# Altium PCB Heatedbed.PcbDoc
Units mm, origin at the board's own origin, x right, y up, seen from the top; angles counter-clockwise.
Board outline 257 x 229 mm, 2 copper layers (Top Layer, Bottom Layer); 12 components, 3 nets, 16 pads, 0 vias.
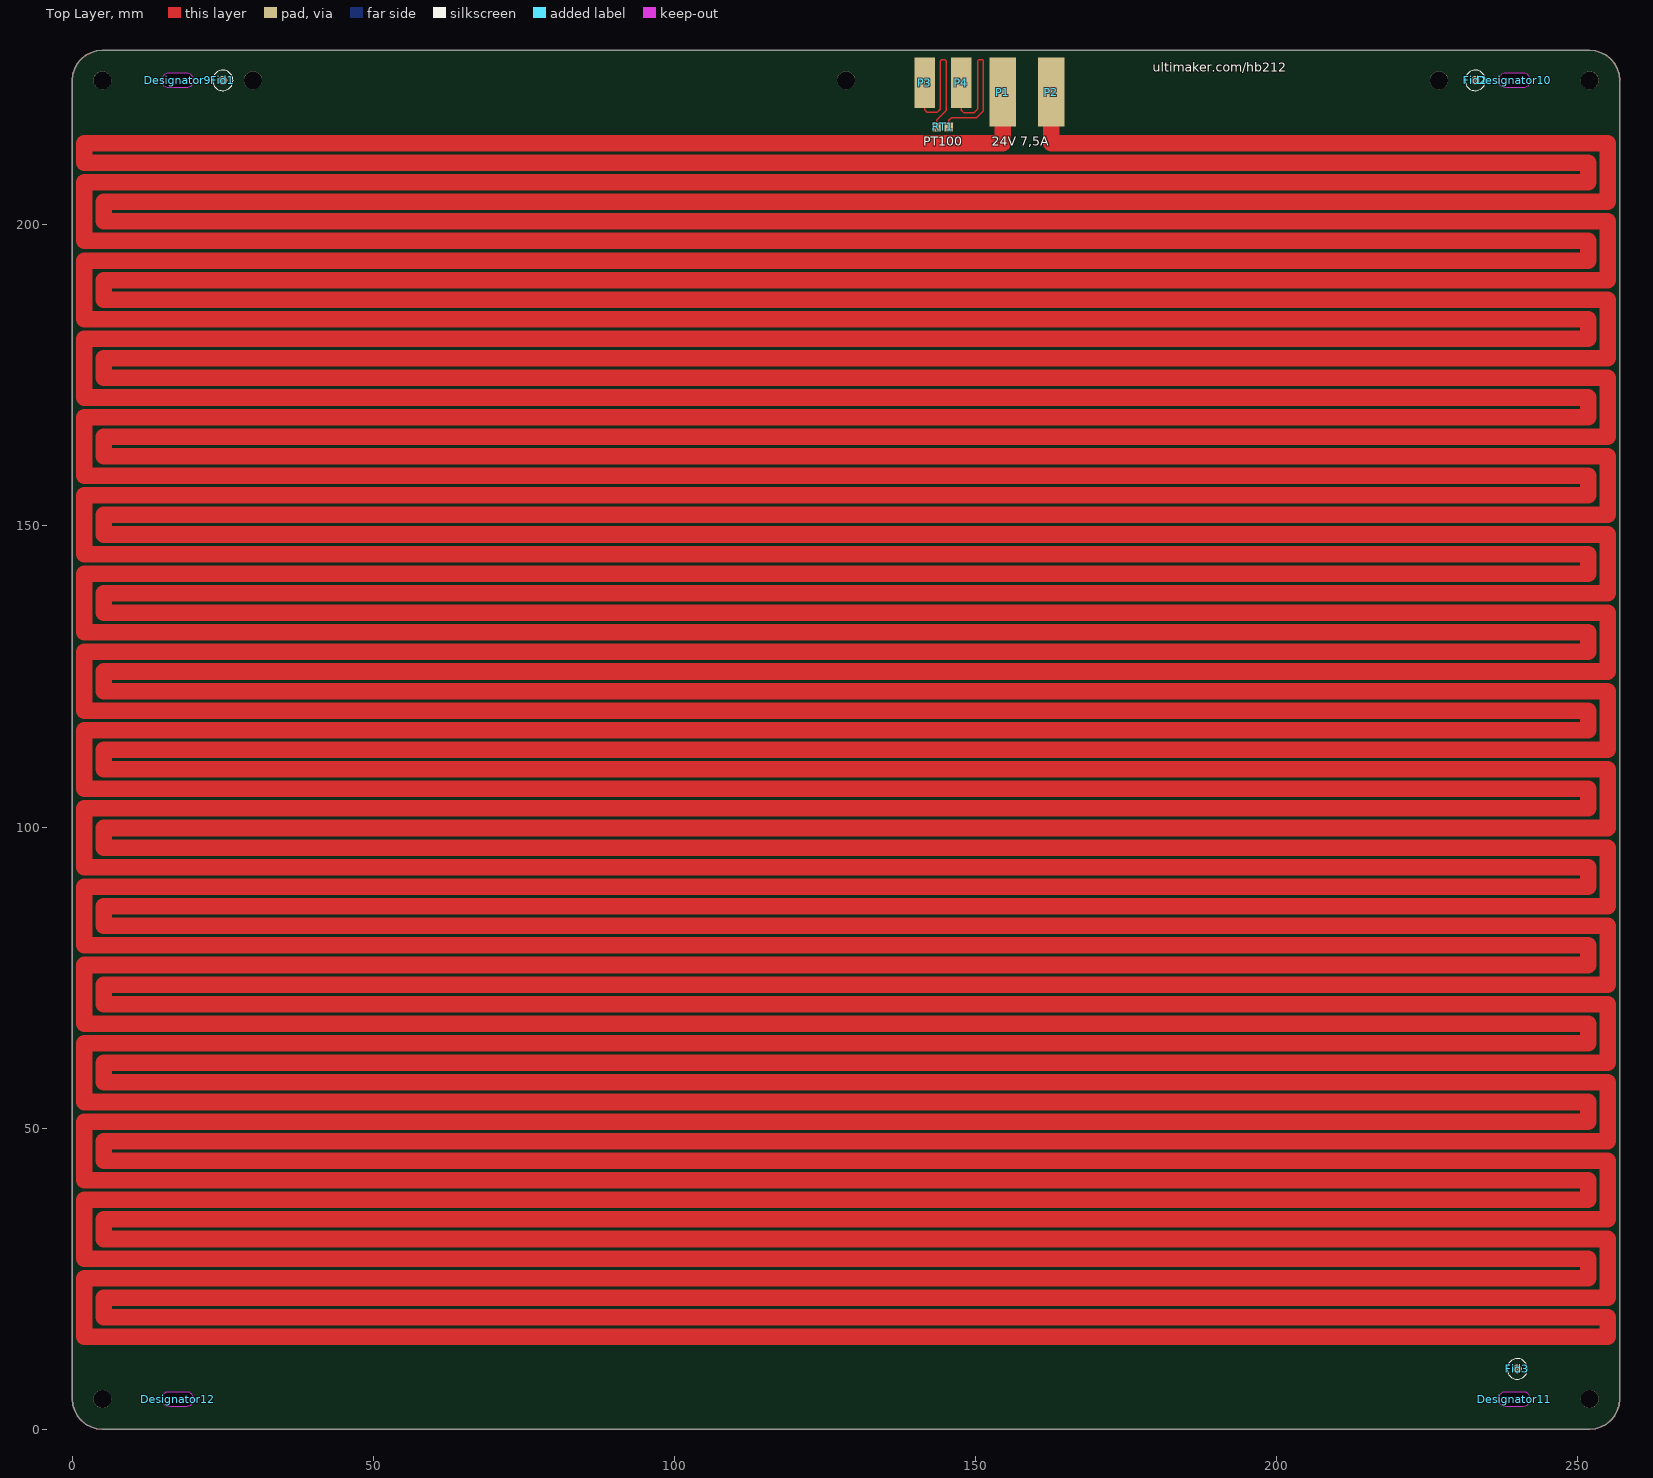
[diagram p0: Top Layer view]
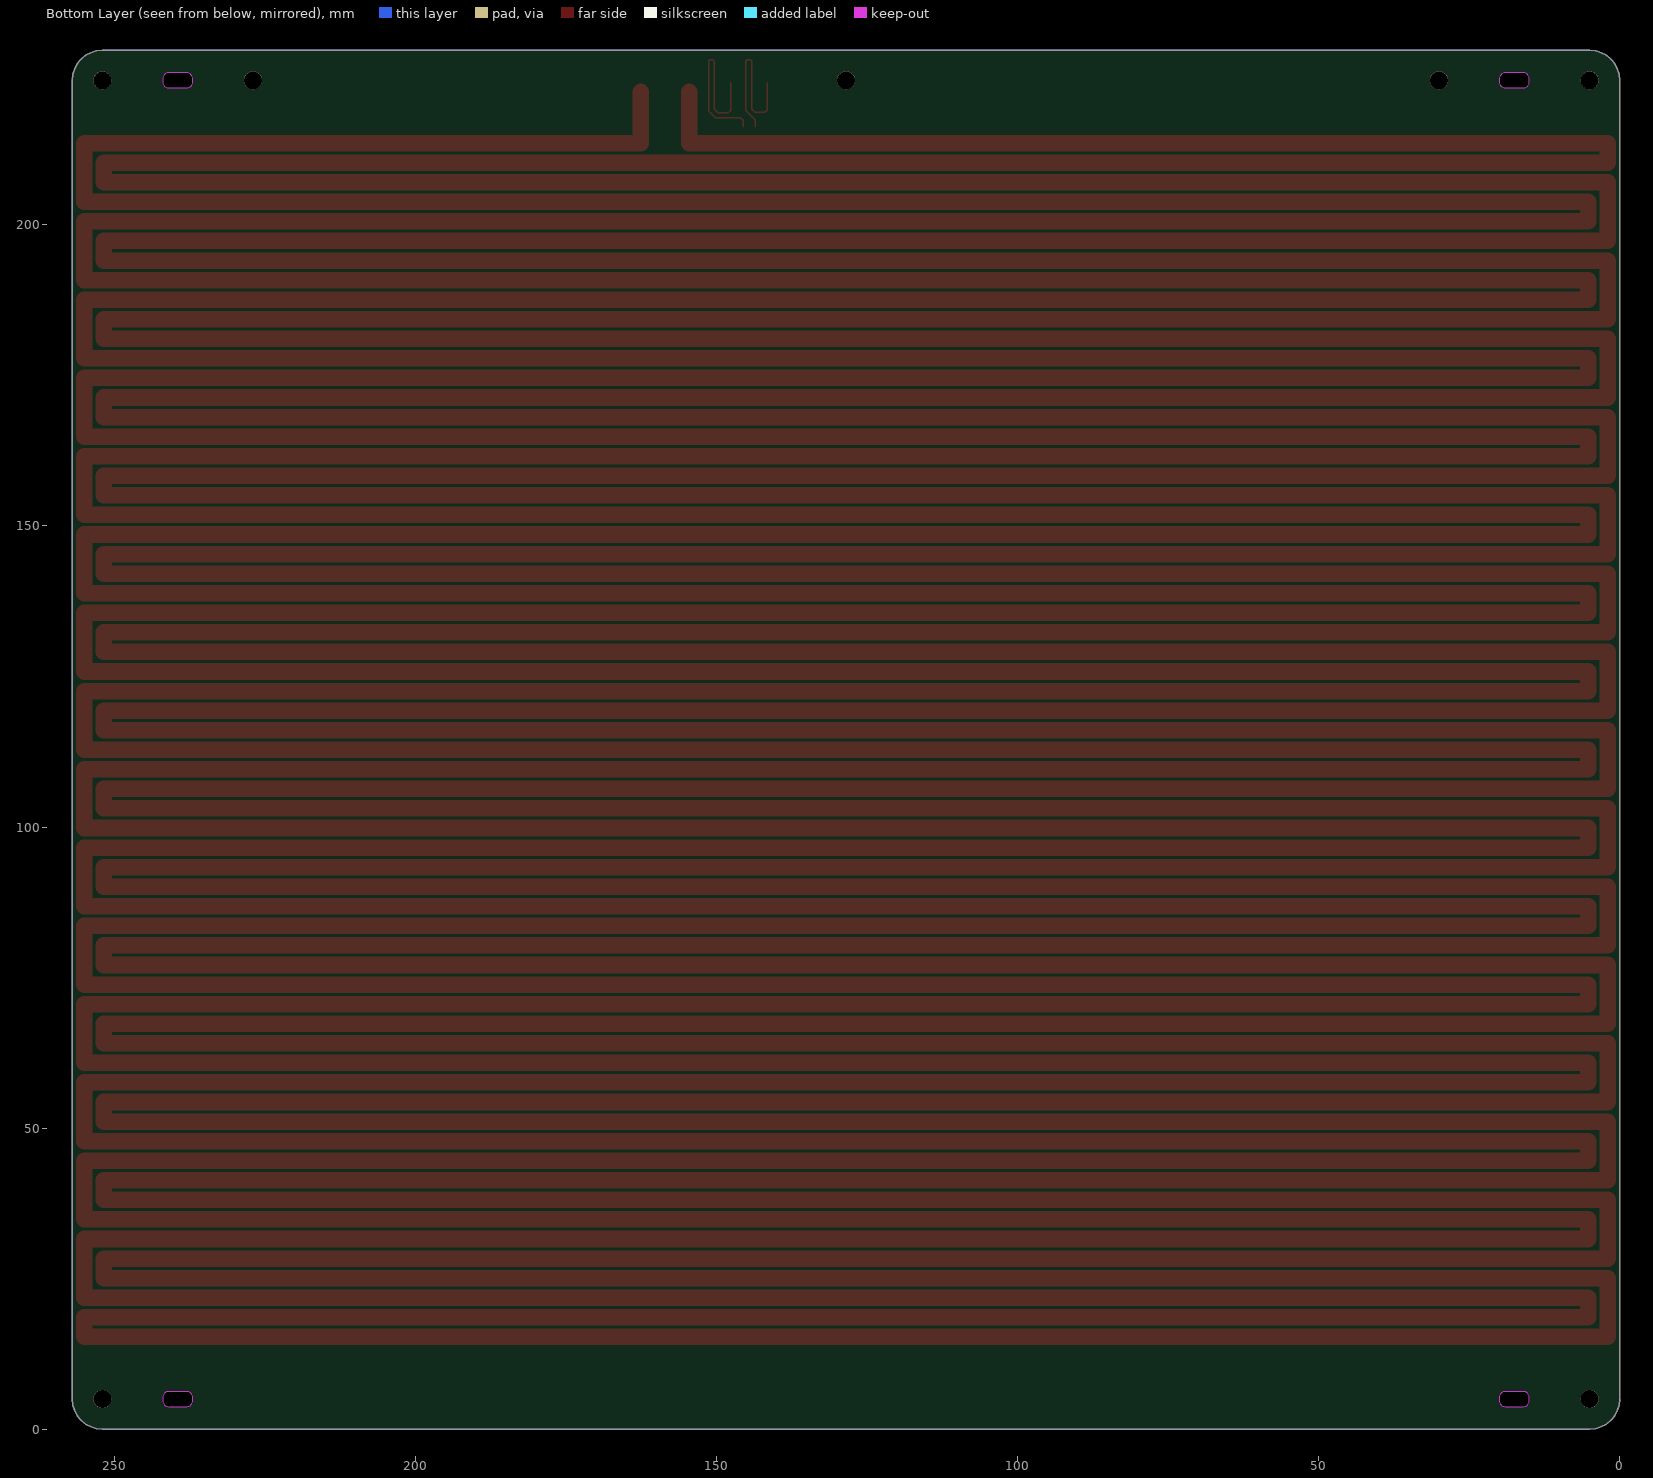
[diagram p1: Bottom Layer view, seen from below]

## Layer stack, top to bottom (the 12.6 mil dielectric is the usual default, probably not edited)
Top Solder: solder mask 0.0102, Solder Resist, Dk 3.5
Top Layer: signal copper 0.0356
Dielectric 1: dielectric 0.32, FR-4, Dk 4.8
Bottom Layer: signal copper 0.0356
Bottom Solder: solder mask 0.0102, Solder Resist, Dk 3.5

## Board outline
0.381,3.086 0.097,4.023 0,4.999 0,224.002 0.097,224.978 0.381,225.915 0.843,226.779 1.463,227.538 2.222,228.158 3.086,228.62 4.023,228.905 5.001,229.001 251.998,229.001 252.976,228.905 253.914,228.62 254.777,228.158 255.534,227.538 256.156,226.779 256.619,225.915 256.903,224.978 257,224.002 257,4.999 256.903,4.023 256.619,3.086 256.156,2.222 255.534,1.463 254.777,0.841 253.914,0.381 252.976,0.094 251.998,0 5.002,0 4.023,0.094 3.086,0.381 2.222,0.841 1.463,1.463 0.843,2.222

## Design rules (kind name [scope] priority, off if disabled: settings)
Clearance [All] p1: gap=0.203
HoleSize [All] p1: absolutevalues=TRUE maxlimit=4.3 minlimit=0.025 maxpercent=80.000 minpercent=20.000
MinimumSolderMaskSliver [All] p1 off: minsoldermaskwidth=0.051
PlaneClearance [All] p1: clearance=0.203
PlaneConnect [All] p1: planeconnectstyle=Relief reliefexpansion=0.203 reliefentries=4 reliefconductorwidth=0.203 reliefairgap=0.203
PolygonConnect [All] p1: connectstyle=Relief reliefconductorwidth=0.254 reliefentries=4 polygonreliefangle="90 Angle" airgapwidth=0.254
RoomDefinition Heatedbed [InComponentClass('Heatedbed')] p1 off: confinementstyle=ConfineIn formatcopy=TRUE lockcomponents=FALSE outline 301.042,-142.701 318.392,-142.701 318.392,-138.126 301.042,-138.126
RoutingVias [All] p1: holewidth=0.3 width=0.6 viastyle="Through Hole" minholewidth=0.3 minwidth=0.6 maxholewidth=1 maxwidth=3
SilkToSilkClearance [All] p1: silktosilkclearance=0
SilkToSolderMaskClearance SilkscreenOverComponentPads [IsPad] p1: minsilkscreentomaskgap=0.127 clearancetoexposedcopper=TRUE
SolderMaskExpansion [All] p1: expansion=0.102
Width [All] p1: maxlimit=10 minlimit=0.203 preferedwidth=0.203
24 further rules are at their usual default settings.

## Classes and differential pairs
component class Heatedbed: Fid1 Fid2 Fid3 P1 P2 P3 P4 RT1

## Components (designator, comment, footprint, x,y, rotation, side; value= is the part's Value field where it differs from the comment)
Designator9 "Comment" Hole 17.5,224 r0 top locked
Designator10 "Comment" Hole 239.5,224 r0 top locked
Designator11 "Comment" Hole 239.5,5 r0 top locked
Designator12 "Comment" Hole 17.5,5 r0 top locked
Fid1 "Fiducial" FIDUCIAL 25,224 r0 top locked
Fid2 "Fiducial" FIDUCIAL 233,224 r0 top locked
Fid3 "Fiducial" FIDUCIAL 240,10 r0 top locked
P1 "Power 1" "AVX POKE HOME CONTACT" 154.56,222.069 r90 top locked
P2 "Power 2" "AVX POKE HOME CONTACT" 162.56,222.069 r90 top locked
P3 "PT100 1" "AVX POKE HOME CONTACT 3MM" 141.6,223.575 r90 top
P4 "PT100 2" "AVX POKE HOME CONTACT 3MM" 147.65,223.575 r90 top
RT1 "PT100 0805" 6-0805_M 144.575,216.275 r0 top locked

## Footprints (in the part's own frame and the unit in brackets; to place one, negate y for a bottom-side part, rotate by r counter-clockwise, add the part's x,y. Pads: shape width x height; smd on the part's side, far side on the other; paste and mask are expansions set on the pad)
6-0805_M [mm] "Chip Resistor, Body 2.0x1.2mm, IPC Low Density"
  rect 1.4x1.5 smd: 1(-1,0) 2(1,0)
  silkscreen extent 0,-0.65 0,0.65, body extent -1.07,-0.7 1.07,0.7, height 0.7
"AVX POKE HOME CONTACT" [mm] "AVX 70-9296-001-004-006"
  rect 11.4x4.4 smd: 1(0,0)
  body extent -5.5,-2 5.5,2, height 4
"AVX POKE HOME CONTACT 3MM" [mm] "AVX 70-9296-001-003-006"
  rect 8.4x3.4 smd: 1(0,0)
  body extent -4,-1.5 4,1.5, height 3
FIDUCIAL [mm] "Fiducial"
  round 1.5 smd paste-20 mask+0.9: ""(0,0)
  silkscreen extent -1.7,-1.7 1.7,1.7
Hole [mm]
  Keep-Out Layer board cut-out: -2.331,-0.805 -2.424,-0.633 -2.481,-0.445 -2.499,-0.25 -2.499,0.25 -2.481,0.445 -2.424,0.633 -2.331,0.806 -2.207,0.957 -2.055,1.081 -1.882,1.174 -1.695,1.23 -1.5,1.25 1.5,1.25 1.696,1.23 1.883,1.174 2.057,1.081 2.207,0.957 2.333,0.806 2.425,0.633 2.481,0.445 2.501,0.25 2.501,-0.25 2.481,-0.445 2.425,-0.633 2.333,-0.805 2.207,-0.956 2.057,-1.082 1.883,-1.174 1.696,-1.231 1.5,-1.25 -1.5,-1.25 -1.695,-1.231 -1.882,-1.174 -2.055,-1.082 -2.207,-0.956

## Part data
Fid1 Fid2 Fid3: library part Library_MISC-0003
P1 P2 P3 P4: library part Plug, "Plug"
RT1: library part "Res Thermal", "Thermistor"

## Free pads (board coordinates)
  round 3 hole 3 unplated: 0(5,5) 0(5,224) 0(30,224) 0(128.5,224) 0(227,224) 0(252,5) 0(252,224)

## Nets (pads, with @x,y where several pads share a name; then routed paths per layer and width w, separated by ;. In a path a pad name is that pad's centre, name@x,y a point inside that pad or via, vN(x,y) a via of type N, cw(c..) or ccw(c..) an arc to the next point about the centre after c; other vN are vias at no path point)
$Net2: P1.1 P2.1 | length 15896.4
  Top Layer w2.751: 1.994,213.589 1.994,210.332 251.744,210.332 251.744,207.081 1.994,207.081 1.994,197.333 251.744,197.333 251.744,194.081 1.994,194.081 1.994,184.333 251.744,184.333 251.744,181.082 1.994,181.082 1.994,171.333 251.744,171.333 251.744,168.082 1.994,168.082 1.994,158.333 251.744,158.333 251.744,155.082 1.994,155.082 1.994,145.331 251.744,145.331 251.744,142.083 1.994,142.083 1.994,132.331 251.744,132.331 251.744,129.083 1.994,129.083 1.994,119.332 251.744,119.332 251.744,116.083 1.994,116.083 1.994,106.332 251.744,106.332 251.744,103.083 1.994,103.083 1.994,93.332 251.744,93.332 251.744,90.081 1.994,90.081 1.994,80.333 251.744,80.333 251.744,77.081 1.994,77.081 1.994,67.333 251.744,67.333 251.744,64.082 1.994,64.082 1.994,54.333 251.744,54.333 251.744,51.082 1.994,51.082 1.994,41.333 251.744,41.333 251.744,38.082 1.994,38.082 1.994,28.331 251.744,28.331 251.744,25.082 1.994,25.082 1.994,15.331 254.993,15.331 254.993,18.583 5.245,18.583 5.245,21.831 254.993,21.831 254.993,31.582 5.245,31.582 5.245,34.831 254.993,34.831 254.993,44.582 5.245,44.582 5.245,47.833 254.993,47.833 254.993,57.582 5.245,57.582 5.245,60.833 254.993,60.833 254.993,70.582 5.245,70.582 5.245,73.833 254.993,73.833 254.993,83.581 5.245,83.581 5.245,86.832 254.993,86.832 254.993,96.584 5.245,96.584 5.245,99.832 254.993,99.832 254.993,109.583 5.245,109.583 5.245,112.832 254.993,112.832 254.993,122.583 5.245,122.583 5.245,125.832 254.993,125.832 254.993,135.583 5.245,135.583 5.245,138.831 254.993,138.831 254.993,148.582 5.245,148.582 5.245,151.831 254.993,151.831 254.993,161.582 5.245,161.582 5.245,164.833 254.993,164.833 254.993,174.582 5.245,174.582 5.245,177.833 254.993,177.833 254.993,187.582 5.245,187.582 5.245,190.833 254.993,190.833 254.993,200.581 5.245,200.581 5.245,203.832 254.993,203.832 254.993,213.594 162.56,213.594 P2.1 ; 1.994,213.594 154.56,213.594 P1.1
NetP3_1: P3.1 RT1.1 | length 28.2
  Top Layer w0.254: P3.1 141.6,219.05 141.975,218.675 143.6,218.675 144.15,219.225 144.15,227.225 144.375,227.45 144.925,227.45 145.125,227.25 145.125,218.975 143.575,217.425 RT1.1
NetP4_1: P4.1 RT1.2 | length 32.6
  Top Layer w0.254: RT1.2 145.575,217.375 145.975,217.775 150.15,217.775 151.325,218.95 151.325,227.225 151.125,227.425 150.575,227.425 150.35,227.2 150.35,219.2 149.8,218.65 148.025,218.65 147.65,219.025 P4.1
pads on no net: Fid1. Fid2. Fid3.

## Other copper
Top Layer:
  text "For more mechanical specs see 1155 specsheet" at 269.24,48.133 h3
Multi-Layer:
  the board outline again, w0.127

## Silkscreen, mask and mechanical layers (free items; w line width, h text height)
Top Overlay:
  text "ultimaker.com/hb212" at 179.451,225.425 h1.52
  text "PT100" at 141.325,213.125 h1.52
  text "24V 7,5A" at 152.675,213.125 h1.52
  text "R" at -8.382,-9.652 h200
Drill Drawing:
  lines w0.025: 270.526,38.417 271.796,38.417 271.796,39.688 270.526,39.688 270.526,38.417
  lines w0.381: 268.796,37.274 387.483,37.274 ; 268.796,41.084 387.483,41.084 ; 282.788,33.465 282.788,44.895 ; 300.512,33.465 300.512,44.895 ; 334.691,33.465 334.691,44.895 ; 354.853,33.465 354.853,44.895 ; 367.702,33.465 367.702,44.895 ; 268.796,33.465 387.483,33.465 387.483,44.895 268.796,44.895 268.796,33.465
  text "Symbol" at 271.082,42.227 h1.83
  text "Hit Count" at 283.931,42.227 h1.83
  text "Finished Hole Size" at 301.655,42.227 h1.83
  text "Tollerance" at 335.834,42.227 h1.83
  text "Plated" at 355.996,42.227 h1.83
  text "Hole Type" at 368.845,42.227 h1.83
  text "7" at 283.931,38.417 h1.52
  text "3,00mm (118,1mil)" at 301.655,38.417 h1.52
  text "+0,08/-0,00" at 335.834,38.417 h1.52
  text "NPTH" at 355.996,38.417 h1.52
  text "Round" at 368.845,38.417 h1.52
  text "7 Total" at 283.931,34.608 h1.52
